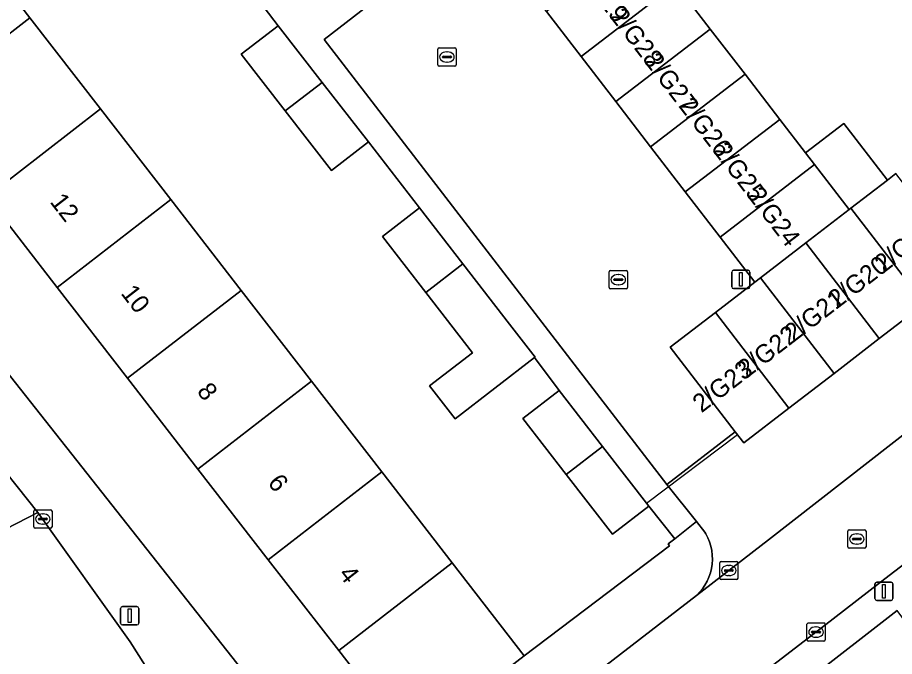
# Model space of a CAD drawing. Extents: x 159217 to 160349, y 381246 to 382172.
# Drawn here: x 159660.85 to 159708.81, y 381439.13 to 381474.09 of the extents above; entities that cross this region are included whole.
import ezdxf

# ---------------------------------------------------------------- set-up
doc = ezdxf.new("R2010")
doc.units = 0
for name, color, linetype in [('IMGEO_Erf', 7, 'Continuous'), ('IMGEO_Hek', 7, 'Continuous'), ('IMGEO_Kolk', 7, 'Continuous'), ('IMGEO_Lichtmast', 7, 'Continuous'), ('IMGEO_Muur', 7, 'Continuous'), ('IMGEO_Pand', 7, 'Continuous'), ('IMGEO_Pand_nummerreeks', 7, 'Continuous'), ('IMGEO_Rijbaan_lokaal_open', 7, 'Continuous'), ('IMGEO_Rioolput', 7, 'Continuous'), ('IMGEO_Voetpad_open', 7, 'Continuous')]:
    doc.layers.add(name, color=color, linetype=linetype)

msp = doc.modelspace()

# ---------------------------------------------------------------- linework, layer by layer
at = {"layer": 'IMGEO_Erf'}
for points in [[(159710.045, 381483.819), (159707.965, 381486.57), (159702.934, 381482.675), (159697.786, 381478.69), (159696.084, 381480.888), (159693.022, 381484.841), (159691.141, 381483.338), (159693.04, 381480.868), (159694.94, 381478.398), (159696.839, 381475.928), (159698.738, 381473.458), (159700.637, 381470.988), (159702.537, 381468.518), (159703.945, 381466.687), (159706.038, 381468.296), (159708.422, 381465.195), (159708.891, 381465.556)], [(159657.568, 381479.184), (159661.532, 381474.067), (159665.385, 381469.092), (159669.232, 381464.125), (159673.08, 381459.157), (159676.927, 381454.191), (159680.774, 381449.223), (159684.622, 381444.255), (159685.503, 381443.118), (159688.565, 381439.165), (159696.508, 381445.174), (159696.438, 381445.284), (159696.797, 381445.57), (159695.378, 381447.353), (159693.388, 381445.811), (159690.855, 381449.082), (159688.482, 381452.146), (159690.472, 381453.687), (159689.126, 381455.481), (159684.79, 381452.124), (159683.39, 381453.932), (159685.738, 381455.75), (159683.188, 381459.042), (159680.814, 381462.108), (159682.83, 381463.669), (159680.043, 381467.282), (159678.02, 381465.715), (159675.494, 381468.977), (159673.092, 381472.078), (159675.115, 381473.645), (159665.99, 381485.608)], [(159658.538, 381456.878), (159678.665, 381431.396), (159682.358, 381434.357), (159678.415, 381439.448), (159674.568, 381444.415), (159670.72, 381449.382), (159666.873, 381454.35), (159663.026, 381459.316), (159659.178, 381464.284)]]:
    msp.add_lwpolyline(points, dxfattribs=at)
msp.add_lwpolyline([(159695.473, 381467.017), (159693.574, 381469.487), (159691.675, 381471.957), (159689.776, 381474.427), (159687.876, 381476.897), (159686.075, 381479.24), (159685.977, 381479.367), (159677.614, 381472.891), (159696.363, 381448.545), (159700.107, 381451.423), (159696.548, 381456.052), (159699.018, 381457.951), (159701.171, 381459.607), (159699.272, 381462.077), (159697.372, 381464.547)], close=True, dxfattribs=at)
at = {"layer": 'IMGEO_Hek'}
msp.add_lwpolyline([(159695.255, 381447.512), (159700.218, 381451.279)], dxfattribs=at)
at = {"layer": 'IMGEO_Kolk'}
for p, q in [((159683.838, 381471.507), (159683.838, 381472.359)), ((159683.913, 381472.433), (159684.765, 381472.433)), ((159684.326, 381472.213), (159684.351, 381472.213)), ((159684.839, 381472.359), (159684.839, 381471.507)), ((159684.097, 381471.927), (159684.097, 381471.939)), ((159684.535, 381471.89), (159684.137, 381471.89)), ((159684.14, 381471.976), (159684.538, 381471.976)), ((159684.581, 381471.939), (159684.581, 381471.927)), ((159684.765, 381471.433), (159683.913, 381471.433)), ((159684.349, 381471.653), (159684.324, 381471.653)), ((159693.207, 381459.321), (159693.207, 381460.173)), ((159693.282, 381460.247), (159694.134, 381460.247)), ((159694.208, 381460.173), (159694.208, 381459.321)), ((159693.466, 381459.741), (159693.466, 381459.753)), ((159693.904, 381459.704), (159693.506, 381459.704)), ((159693.509, 381459.79), (159693.907, 381459.79)), ((159693.695, 381460.027), (159693.72, 381460.027)), ((159693.95, 381459.753), (159693.95, 381459.741)), ((159694.134, 381459.247), (159693.282, 381459.247)), ((159693.718, 381459.467), (159693.693, 381459.467)), ((159661.738, 381446.224), (159661.738, 381447.076)), ((159661.813, 381447.15), (159662.665, 381447.15)), ((159662.226, 381446.93), (159662.251, 381446.93)), ((159662.739, 381447.076), (159662.739, 381446.224)), ((159661.997, 381446.644), (159661.997, 381446.656)), ((159662.435, 381446.607), (159662.037, 381446.607)), ((159662.04, 381446.693), (159662.438, 381446.693)), ((159662.249, 381446.37), (159662.224, 381446.37)), ((159662.481, 381446.656), (159662.481, 381446.644)), ((159662.665, 381446.15), (159661.813, 381446.15)), ((159699.252, 381443.405), (159699.252, 381444.257)), ((159699.327, 381444.331), (159700.179, 381444.331)), ((159699.554, 381443.874), (159699.952, 381443.874)), ((159699.74, 381444.111), (159699.765, 381444.111)), ((159700.253, 381444.257), (159700.253, 381443.405)), ((159699.511, 381443.825), (159699.511, 381443.837)), ((159699.949, 381443.788), (159699.551, 381443.788)), ((159699.763, 381443.551), (159699.738, 381443.551)), ((159699.995, 381443.837), (159699.995, 381443.825)), ((159700.179, 381443.331), (159699.327, 381443.331)), ((159704.022, 381440.034), (159704.022, 381440.886)), ((159704.097, 381440.96), (159704.949, 381440.96)), ((159704.51, 381440.74), (159704.535, 381440.74)), ((159705.023, 381440.886), (159705.023, 381440.034)), ((159704.281, 381440.454), (159704.281, 381440.466)), ((159704.719, 381440.417), (159704.321, 381440.417)), ((159704.324, 381440.503), (159704.722, 381440.503)), ((159704.533, 381440.18), (159704.508, 381440.18)), ((159704.765, 381440.466), (159704.765, 381440.454)), ((159704.949, 381439.96), (159704.097, 381439.96))]:
    msp.add_line(p, q, dxfattribs=at)
for points in [[(159683.838, 381471.507), (159683.838, 381472.359)], [(159683.913, 381472.433), (159684.765, 381472.433)], [(159684.839, 381472.359), (159684.839, 381471.507)], [(159684.765, 381471.433), (159683.913, 381471.433)], [(159693.207, 381459.321), (159693.207, 381460.173)], [(159693.282, 381460.247), (159694.134, 381460.247)], [(159694.208, 381460.173), (159694.208, 381459.321)], [(159694.134, 381459.247), (159693.282, 381459.247)], [(159661.738, 381446.224), (159661.738, 381447.076)], [(159661.813, 381447.15), (159662.665, 381447.15)], [(159662.739, 381447.076), (159662.739, 381446.224)], [(159662.665, 381446.15), (159661.813, 381446.15)], [(159699.252, 381443.405), (159699.252, 381444.257)], [(159699.327, 381444.331), (159700.179, 381444.331)], [(159700.253, 381444.257), (159700.253, 381443.405)], [(159700.179, 381443.331), (159699.327, 381443.331)], [(159704.022, 381440.034), (159704.022, 381440.886)], [(159704.097, 381440.96), (159704.949, 381440.96)], [(159705.023, 381440.886), (159705.023, 381440.034)], [(159704.949, 381439.96), (159704.097, 381439.96)]]:
    msp.add_lwpolyline(points, dxfattribs=at)
for centre, radius, start, end in [((159683.915, 381472.357), 0.0765, 91.552, 178.448), ((159683.915, 381472.357), 0.0765, 91.552, 178.448), ((159684.763, 381472.357), 0.0765, 1.552, 88.448), ((159684.763, 381472.357), 0.0765, 1.552, 88.448), ((159684.137, 381471.936), 0.0403, 85.8775, 175.7526), ((159684.134, 381471.926), 0.0366, 178.938, 274.7102), ((159684.538, 381471.933), 0.043, 264.8664, 352.4533), ((159684.542, 381471.938), 0.0386, 1.7309, 96.639), ((159683.915, 381471.509), 0.0765, 181.552, 268.448), ((159683.915, 381471.509), 0.0765, 181.552, 268.448), ((159684.763, 381471.509), 0.0765, 271.552, 358.448), ((159684.763, 381471.509), 0.0765, 271.552, 358.448), ((159693.284, 381460.171), 0.0765, 91.552, 178.448), ((159693.284, 381460.171), 0.0765, 91.552, 178.448), ((159694.132, 381460.171), 0.0765, 1.552, 88.448), ((159694.132, 381460.171), 0.0765, 1.552, 88.448), ((159693.506, 381459.75), 0.0403, 85.8775, 175.7526), ((159693.503, 381459.74), 0.0366, 178.938, 274.7102), ((159693.907, 381459.747), 0.043, 264.8664, 352.4533), ((159693.911, 381459.752), 0.0386, 1.7309, 96.639), ((159693.284, 381459.323), 0.0765, 181.552, 268.448), ((159693.284, 381459.323), 0.0765, 181.552, 268.448), ((159694.132, 381459.323), 0.0765, 271.552, 358.448), ((159694.132, 381459.323), 0.0765, 271.552, 358.448), ((159661.815, 381447.074), 0.0765, 91.552, 178.448), ((159661.815, 381447.074), 0.0765, 91.552, 178.448), ((159662.663, 381447.074), 0.0765, 1.552, 88.448), ((159662.663, 381447.074), 0.0765, 1.552, 88.448), ((159662.037, 381446.653), 0.0403, 85.8775, 175.7526), ((159662.034, 381446.643), 0.0366, 178.938, 274.7102), ((159662.438, 381446.65), 0.043, 264.8664, 352.4533), ((159662.442, 381446.655), 0.0386, 1.7309, 96.639), ((159661.815, 381446.226), 0.0765, 181.552, 268.448), ((159661.815, 381446.226), 0.0765, 181.552, 268.448), ((159662.663, 381446.226), 0.0765, 271.552, 358.448), ((159662.663, 381446.226), 0.0765, 271.552, 358.448), ((159699.329, 381444.255), 0.0765, 91.552, 178.448), ((159699.329, 381444.255), 0.0765, 91.552, 178.448), ((159699.551, 381443.834), 0.0403, 85.8775, 175.7526), ((159699.956, 381443.836), 0.0386, 1.7309, 96.639), ((159700.177, 381444.255), 0.0765, 1.552, 88.448), ((159700.177, 381444.255), 0.0765, 1.552, 88.448), ((159699.329, 381443.407), 0.0765, 181.552, 268.448), ((159699.329, 381443.407), 0.0765, 181.552, 268.448), ((159699.548, 381443.824), 0.0366, 178.938, 274.7102), ((159699.952, 381443.831), 0.043, 264.8664, 352.4533), ((159700.177, 381443.407), 0.0765, 271.552, 358.448), ((159700.177, 381443.407), 0.0765, 271.552, 358.448), ((159704.099, 381440.884), 0.0765, 91.552, 178.448), ((159704.099, 381440.884), 0.0765, 91.552, 178.448), ((159704.947, 381440.884), 0.0765, 1.552, 88.448), ((159704.947, 381440.884), 0.0765, 1.552, 88.448), ((159704.099, 381440.036), 0.0765, 181.552, 268.448), ((159704.099, 381440.036), 0.0765, 181.552, 268.448), ((159704.321, 381440.463), 0.0403, 85.8775, 175.7526), ((159704.318, 381440.453), 0.0366, 178.938, 274.7102), ((159704.722, 381440.46), 0.043, 264.8664, 352.4533), ((159704.726, 381440.465), 0.0386, 1.7309, 96.639), ((159704.947, 381440.036), 0.0765, 271.552, 358.448), ((159704.947, 381440.036), 0.0765, 271.552, 358.448)]:
    msp.add_arc(centre, radius, start, end, dxfattribs=at)
for centre, major_axis, ratio, start_param, end_param in [((159684.325, 381471.933), (-0.387, 0.002), 0.722429, 4.712389, 7.853982), ((159684.35, 381471.933), (-0.39, 0.002), 0.717154, 1.570796, 4.712389), ((159693.694, 381459.747), (-0.387, 0.002), 0.722429, 4.712389, 7.853982), ((159693.719, 381459.747), (-0.39, 0.002), 0.717154, 1.570796, 4.712389), ((159662.225, 381446.65), (-0.387, 0.002), 0.722429, 4.712389, 7.853982), ((159662.25, 381446.65), (-0.39, 0.002), 0.717154, 1.570796, 4.712389), ((159699.739, 381443.831), (-0.387, 0.002), 0.722429, 4.712389, 7.853982), ((159699.764, 381443.831), (-0.39, 0.002), 0.717154, 1.570796, 4.712389), ((159704.509, 381440.46), (-0.387, 0.002), 0.722429, 4.712389, 7.853982), ((159704.534, 381440.46), (-0.39, 0.002), 0.717154, 1.570796, 4.712389)]:
    msp.add_ellipse(centre, major_axis=major_axis, ratio=ratio, start_param=start_param, end_param=end_param, dxfattribs=at)
at = {"layer": 'IMGEO_Lichtmast'}
for p, q in [((159700.013, 381460.257), (159700.803, 381460.257)), ((159700.803, 381460.257), (159700.013, 381460.257)), ((159699.913, 381459.357), (159699.913, 381460.157)), ((159699.913, 381460.157), (159699.913, 381459.357)), ((159700.903, 381460.157), (159700.903, 381459.357)), ((159700.903, 381459.357), (159700.903, 381460.157)), ((159700.803, 381459.257), (159700.013, 381459.257)), ((159700.013, 381459.257), (159700.803, 381459.257)), ((159707.738, 381442.293), (159707.738, 381443.093)), ((159707.738, 381443.093), (159707.738, 381442.293)), ((159707.838, 381443.193), (159708.628, 381443.193)), ((159708.628, 381443.193), (159707.838, 381443.193)), ((159708.728, 381443.093), (159708.728, 381442.293)), ((159708.728, 381442.293), (159708.728, 381443.093)), ((159708.628, 381442.193), (159707.838, 381442.193)), ((159707.838, 381442.193), (159708.628, 381442.193)), ((159666.491, 381440.953), (159666.491, 381441.753)), ((159666.491, 381441.753), (159666.491, 381440.953)), ((159666.591, 381441.853), (159667.381, 381441.853)), ((159667.381, 381441.853), (159666.591, 381441.853)), ((159667.481, 381441.753), (159667.481, 381440.953)), ((159667.481, 381440.953), (159667.481, 381441.753)), ((159667.381, 381440.853), (159666.591, 381440.853)), ((159666.591, 381440.853), (159667.381, 381440.853))]:
    msp.add_line(p, q, dxfattribs=at)
for points in [[(159700.333, 381460.132), (159700.483, 381460.132), (159700.483, 381459.382), (159700.333, 381459.382), (159700.333, 381460.132)], [(159708.158, 381443.068), (159708.308, 381443.068), (159708.308, 381442.318), (159708.158, 381442.318), (159708.158, 381443.068)], [(159666.911, 381441.728), (159667.061, 381441.728), (159667.061, 381440.978), (159666.911, 381440.978), (159666.911, 381441.728)]]:
    msp.add_lwpolyline(points, dxfattribs=at)
for centre, start, end in [((159700.013, 381460.157), 90, 180), ((159700.013, 381460.157), 90, 180), ((159700.803, 381460.157), 0, 90), ((159700.803, 381460.157), 360, 90), ((159700.013, 381459.357), 180, 270), ((159700.013, 381459.357), 180, 270), ((159700.803, 381459.357), 270, 0), ((159700.803, 381459.357), 270, 0), ((159707.838, 381443.093), 90, 180), ((159707.838, 381443.093), 90, 180), ((159708.628, 381443.093), 0, 90), ((159708.628, 381443.093), 360, 90), ((159707.838, 381442.293), 180, 270), ((159707.838, 381442.293), 180, 270), ((159708.628, 381442.293), 270, 0), ((159708.628, 381442.293), 270, 0), ((159666.591, 381441.753), 90, 180), ((159666.591, 381441.753), 90, 180), ((159667.381, 381441.753), 0, 90), ((159667.381, 381441.753), 360, 90), ((159666.591, 381440.953), 180, 270), ((159666.591, 381440.953), 180, 270), ((159667.381, 381440.953), 270, 0), ((159667.381, 381440.953), 270, 0)]:
    msp.add_arc(centre, 0.1, start, end, dxfattribs=at)
at = {"layer": 'IMGEO_Muur'}
msp.add_lwpolyline([(159688.565, 381439.165), (159696.508, 381445.174)], dxfattribs=at)
at = {"layer": 'IMGEO_Pand'}
for points in [[(159657.568, 381479.184), (159653.355, 381475.921), (159651.361, 381474.376), (159655.324, 381469.259), (159661.532, 381474.067)], [(159694.94, 381478.398), (159689.776, 381474.427), (159691.675, 381471.957), (159696.839, 381475.928)], [(159698.738, 381473.458), (159696.839, 381475.928), (159691.675, 381471.957), (159693.574, 381469.487)], [(159665.385, 381469.092), (159661.532, 381474.067), (159655.324, 381469.259), (159659.178, 381464.284)], [(159675.494, 381468.977), (159677.516, 381470.544), (159675.115, 381473.645), (159673.092, 381472.078)], [(159698.738, 381473.458), (159693.574, 381469.487), (159695.473, 381467.017), (159700.637, 381470.988)], [(159697.372, 381464.547), (159702.537, 381468.518), (159700.637, 381470.988), (159695.473, 381467.017)], [(159675.494, 381468.977), (159678.02, 381465.715), (159680.043, 381467.282), (159677.516, 381470.544)], [(159665.385, 381469.092), (159659.178, 381464.284), (159663.026, 381459.316), (159669.232, 381464.125)], [(159704.436, 381466.048), (159703.945, 381466.687), (159702.537, 381468.518), (159697.372, 381464.547), (159699.272, 381462.077)], [(159703.945, 381466.687), (159704.436, 381466.048), (159706.329, 381463.586), (159706.421, 381463.657), (159708.422, 381465.195), (159706.038, 381468.296)], [(159699.272, 381462.077), (159701.171, 381459.607), (159701.487, 381459.851), (159703.954, 381461.754), (159706.329, 381463.586), (159704.436, 381466.048)], [(159708.891, 381465.556), (159708.422, 381465.195), (159706.421, 381463.657), (159710.45, 381458.418), (159712.92, 381460.317)], [(159663.026, 381459.316), (159666.873, 381454.35), (159673.08, 381459.157), (159669.232, 381464.125)], [(159683.188, 381459.042), (159685.204, 381460.604), (159682.83, 381463.669), (159680.814, 381462.108)], [(159706.421, 381463.657), (159706.329, 381463.586), (159703.954, 381461.754), (159707.98, 381456.518), (159710.45, 381458.418)], [(159701.487, 381459.851), (159705.51, 381454.619), (159707.98, 381456.518), (159703.954, 381461.754)], [(159685.204, 381460.604), (159683.188, 381459.042), (159685.738, 381455.75), (159683.39, 381453.932), (159684.79, 381452.124), (159689.126, 381455.481), (159689.154, 381455.503), (159687.754, 381457.311)], [(159703.04, 381452.72), (159705.51, 381454.619), (159701.487, 381459.851), (159701.171, 381459.607), (159699.018, 381457.951)], [(159670.72, 381449.382), (159676.927, 381454.191), (159673.08, 381459.157), (159666.873, 381454.35)], [(159699.018, 381457.951), (159696.548, 381456.052), (159700.107, 381451.423), (159700.57, 381450.821), (159703.04, 381452.72)], [(159670.72, 381449.382), (159674.568, 381444.415), (159680.774, 381449.223), (159676.927, 381454.191)], [(159692.845, 381450.623), (159690.472, 381453.687), (159688.482, 381452.146), (159690.855, 381449.082)], [(159692.845, 381450.623), (159690.855, 381449.082), (159693.388, 381445.811), (159695.378, 381447.353)], [(159678.415, 381439.448), (159684.622, 381444.255), (159680.774, 381449.223), (159674.568, 381444.415)], [(159678.415, 381439.448), (159682.358, 381434.357), (159688.565, 381439.165), (159685.503, 381443.118), (159684.622, 381444.255)], [(159713.312, 381435.732), (159708.96, 381441.635), (159703.954, 381437.761), (159708.444, 381431.965)]]:
    msp.add_lwpolyline(points, close=True, dxfattribs=at)
at = {"layer": 'IMGEO_Rijbaan_lokaal_open'}
for points in [[(159622.722, 381481.996), (159634.378, 381468.127), (159644.872, 381455.298), (159653.953, 381443.607), (159654.315, 381443.064), (159661.967, 381447.007), (159656.153, 381454.295), (159649.268, 381462.862), (159641.019, 381472.846)], [(159718.274, 381458.259), (159701.918, 381445.502), (159697.98, 381442.46), (159688.867, 381435.418), (159680.565, 381429.027), (159678.071, 381427.063), (159680.529, 381421.765), (159683.372, 381424.074), (159689.16, 381428.611), (159691.194, 381430.18), (159693.644, 381432.07), (159700.32, 381437.219), (159705.454, 381441.178), (159708.054, 381443.186), (159710.157, 381444.811)], [(159710.45, 381458.418), (159707.98, 381456.518), (159705.51, 381454.619), (159703.04, 381452.72), (159700.57, 381450.821), (159700.107, 381451.423), (159696.363, 381448.545), (159697.986, 381446.516), (159698.438, 381445.932), (159698.49, 381445.846), (159698.603, 381445.627), (159698.696, 381445.399), (159698.768, 381445.164), (159698.819, 381444.923), (159698.848, 381444.678), (159698.855, 381444.432), (159698.841, 381444.186), (159698.804, 381443.943), (159698.746, 381443.704), (159698.666, 381443.47), (159698.566, 381443.245), (159698.447, 381443.03), (159698.308, 381442.826), (159698.152, 381442.636), (159697.98, 381442.46), (159701.918, 381445.502), (159718.274, 381458.259)], [(159660.551, 381432.248), (159660.995, 381432.073), (159661.433, 381431.877), (159661.945, 381431.597), (159662.429, 381431.272), (159662.505, 381431.216), (159663.013, 381430.8), (159663.482, 381430.34), (159663.908, 381429.84), (159671.548, 381432.756), (159667.02, 381439.927), (159661.967, 381447.007), (159654.315, 381443.064)]]:
    msp.add_lwpolyline(points, dxfattribs=at)
at = {"layer": 'IMGEO_Rioolput'}
for p, q in [((159706.254, 381445.13), (159706.254, 381445.982)), ((159706.329, 381446.056), (159707.181, 381446.056)), ((159706.742, 381445.836), (159706.767, 381445.836)), ((159707.255, 381445.982), (159707.255, 381445.13)), ((159706.513, 381445.55), (159706.513, 381445.562)), ((159706.951, 381445.513), (159706.553, 381445.513)), ((159706.556, 381445.599), (159706.954, 381445.599)), ((159706.997, 381445.562), (159706.997, 381445.55)), ((159707.181, 381445.056), (159706.329, 381445.056)), ((159706.765, 381445.276), (159706.74, 381445.276))]:
    msp.add_line(p, q, dxfattribs=at)
for points in [[(159706.254, 381445.13), (159706.254, 381445.982)], [(159706.329, 381446.056), (159707.181, 381446.056)], [(159707.255, 381445.982), (159707.255, 381445.13)], [(159707.181, 381445.056), (159706.329, 381445.056)]]:
    msp.add_lwpolyline(points, dxfattribs=at)
for centre, radius, start, end in [((159706.331, 381445.98), 0.0765, 91.552, 178.448), ((159706.331, 381445.98), 0.0765, 91.552, 178.448), ((159707.179, 381445.98), 0.0765, 1.552, 88.448), ((159707.179, 381445.98), 0.0765, 1.552, 88.448), ((159706.553, 381445.559), 0.0403, 85.8775, 175.7526), ((159706.55, 381445.549), 0.0366, 178.938, 274.7102), ((159706.954, 381445.556), 0.043, 264.8664, 352.4533), ((159706.958, 381445.561), 0.0386, 1.7309, 96.639), ((159706.331, 381445.132), 0.0765, 181.552, 268.448), ((159706.331, 381445.132), 0.0765, 181.552, 268.448), ((159707.179, 381445.132), 0.0765, 271.552, 358.448), ((159707.179, 381445.132), 0.0765, 271.552, 358.448)]:
    msp.add_arc(centre, radius, start, end, dxfattribs=at)
for centre, major_axis, ratio, start_param, end_param in [((159706.741, 381445.556), (-0.387, 0.002), 0.722429, 4.712389, 7.853982), ((159706.766, 381445.556), (-0.39, 0.002), 0.717154, 1.570796, 4.712389)]:
    msp.add_ellipse(centre, major_axis=major_axis, ratio=ratio, start_param=start_param, end_param=end_param, dxfattribs=at)
at = {"layer": 'IMGEO_Voetpad_open'}
for points in [[(159623.689, 381499.86), (159623.773, 381500), (159624.547, 381501.291), (159619.537, 381497.357), (159622.028, 381494.6), (159627.569, 381488.79), (159632.882, 381482.53), (159641.019, 381472.846), (159649.268, 381462.862), (159656.153, 381454.295), (159661.967, 381447.007), (159667.02, 381439.927), (159671.548, 381432.756), (159673.95, 381428.491), (159675.233, 381425.821), (159678.071, 381427.063), (159680.565, 381429.027), (159678.665, 381431.396), (159658.538, 381456.878), (159645.679, 381472.593), (159623.993, 381498.112)], [(159665.99, 381485.608), (159675.115, 381473.645), (159677.516, 381470.544), (159680.043, 381467.282), (159682.83, 381463.669), (159685.204, 381460.604), (159687.754, 381457.311), (159689.154, 381455.503), (159689.126, 381455.481), (159690.472, 381453.687), (159692.845, 381450.623), (159695.378, 381447.353), (159696.797, 381445.57), (159697.986, 381446.516), (159696.363, 381448.545), (159677.614, 381472.891), (159685.977, 381479.367)], [(159688.867, 381435.418), (159697.98, 381442.46), (159698.152, 381442.636), (159698.308, 381442.826), (159698.447, 381443.03), (159698.566, 381443.245), (159698.666, 381443.47), (159698.746, 381443.704), (159698.804, 381443.943), (159698.841, 381444.186), (159698.855, 381444.432), (159698.848, 381444.678), (159698.819, 381444.923), (159698.768, 381445.164), (159698.696, 381445.399), (159698.603, 381445.627), (159698.49, 381445.846), (159698.438, 381445.932), (159697.986, 381446.516), (159696.797, 381445.57), (159696.438, 381445.284), (159696.508, 381445.174), (159688.565, 381439.165), (159682.358, 381434.357)], [(159710.157, 381444.811), (159708.054, 381443.186), (159705.454, 381441.178), (159700.32, 381437.219), (159693.644, 381432.07), (159691.194, 381430.18), (159689.16, 381428.611), (159683.372, 381424.074), (159680.529, 381421.765), (159680.003, 381421.35), (159680.622, 381419.806), (159683.136, 381421.727), (159687.801, 381425.292), (159692.224, 381428.72), (159692.543, 381428.967), (159694.655, 381430.604), (159699.089, 381434.041), (159701.424, 381435.803), (159703.954, 381437.761), (159708.96, 381441.635)]]:
    msp.add_lwpolyline(points, dxfattribs=at)

# ---------------------------------------------------------------- texts
at = {"layer": 'IMGEO_Pand_nummerreeks'}
for s, rotation, p in [('2/G29', 307.4879, (159691.338, 381476.588)), ('2/G28', 307.4879, (159693.219, 381474.136)), ('2/G27', 307.4879, (159695.094, 381471.69)), ('2/G26', 307.4879, (159696.972, 381469.243)), ('2/G25', 307.4884, (159698.849, 381466.795)), ('2/G24', 307.4879, (159700.727, 381464.347)), ('12', 307.7598, (159662.588, 381463.997)), ('2/G19', 37.5688, (159708.214, 381460.085)), ('2/G20', 37.5686, (159705.675, 381458.132)), ('10', 307.7598, (159666.466, 381458.99)), ('2/G21', 37.5686, (159703.289, 381456.296)), ('2/G22', 37.5686, (159700.725, 381454.324)), ('2/G23', 37.5688, (159698.258, 381452.427)), ('8', 307.7598, (159670.624, 381453.623)), ('6', 307.7598, (159674.495, 381448.624)), ('4', 307.7598, (159678.37, 381443.621))]:
    msp.add_text(s, height=1, rotation=rotation, dxfattribs=at).set_placement(p)

doc.saveas('drawing.dxf')
